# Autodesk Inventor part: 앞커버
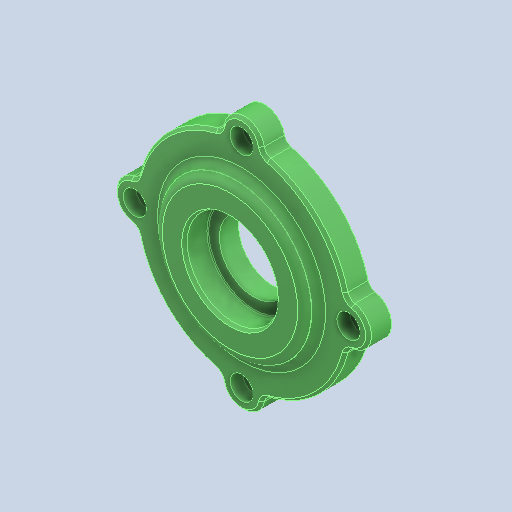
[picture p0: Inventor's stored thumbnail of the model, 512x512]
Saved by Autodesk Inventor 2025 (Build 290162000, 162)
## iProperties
Created: 2024-08
Part Number: 앞커버
Material: 알루미늄 6061
Document SubType Name: Modeling
Designer: Administrator
Density: 2.71 g/cm^3
Appearance: 기본값
Company: 한국ATC센터
Author: jhkim
Sending System: Autodesk Inventor 2025
Preprocessor: ST-DEVELOPER v20
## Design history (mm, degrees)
feature "솔리드1"
node "솔리드2"
